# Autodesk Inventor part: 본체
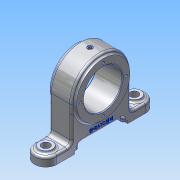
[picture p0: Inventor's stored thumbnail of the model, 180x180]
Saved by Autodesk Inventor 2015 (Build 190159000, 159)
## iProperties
Created: 2019-05
Part Number: 본체
Material: 알루미늄 6061
Document SubType Name: Modeling
Designer: user
Density: 2.7 g/cm^3
Appearance: 알루미늄 - 평지
Mass: 456.342 g
Surface Area: 318.292 cm^2
Volume: 169.015 cm^3
Author: user
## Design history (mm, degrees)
sketch "스케치1" dims "d1" = 80, "d3" = 62
  geometry: L1 (-30, 0)-(110, 0) reference; L2 (50, -40)-(2, -40); L3 (2, -40)-(2, -75); L4 (2, -75)-(-10, -75); L5 (-10, -75)-(-10, -36); L6 (0, -30)-(0, 0); L7 (0, -30)-(-6, -30); L8 (-6, -30)-(-6, -36); L9 (-6, -36)-(-10, -36); L10 (2, 40)-(2, 75); L11 (2, 75)-(-10, 75); L12 (-10, 75)-(-10, 36); L13 (-6, 30)-(-6, 36); L14 (-6, 36)-(-10, 36); L15 (0, 30)-(0, 0); L16 (0, 30)-(-6, 30); L17 (50, 40)-(2, 40); C1 r 26 at (50, 0); A1 r 40 centre (50, 0) between (50, 40) and (50, -40); 4 further points
  constraints: 32 end point, 8 symmetric about line, 4 coincident, 4 horizontal, 3 perpendicular, 2 centre point, 2 horizontal alignment, 2 point on circle, 2 vertical alignment, 1 vertical, 6 other
  dimensions: "d2" = 52 diameter of C1; "d4" = 72 diameter of L9 L1; "d5" = 60 diameter of L7 L1; "d6" = 150 diameter of L4 L1; "d8" = 60 distance from line of L5 point (50, 0); "d9" = 100 dimension on L5 (derived); "d10" = 4 distance of L8.end L5.end; "d11" = 10 distance between parallel lines of L5 L6; "d18" = 12 distance between parallel lines of L5 L3
extrude "돌출1" new body sketch "스케치1" stored distance "d19" = 30; taper "d20" = 0 deg
fillet "모깎기1" dims "d21" = 15
sketch "스케치2"
  geometry: L1 (30, 0)-(30, -20) reference; L2 (0, 0)-(30, 0) reference; L3 (0, -20)-(0, 0) reference; L4 (0, 80)-(0, 100) reference; L5 (0, 80)-(30, 80) reference; L6 (30, 100)-(30, 80) reference; C1 r 9 at (15, -20); A1 r 15 centre (15, -20) between (0, -20) and (30, -20) reference; A2 r 15 centre (15, 100) between (30, 100) and (0, 100) reference; 1 further point
  constraints: 1 centre point, 1 coincident
  dimensions: "d22" = 18 diameter of C1
extrude "돌출2" join sketch "스케치2" distance "d23" = 3; taper "d24" = 0 deg
sketch "스케치3"
  geometry: C1 r 9 at (0, 0) reference; 1 further point
hole "구멍1" sketch "스케치3" at (0, 0) diameter "d25" = 11; stored, may be unused: countersink angle "d29" = 90 deg, drill point angle "d31" = 118 deg; dims "d26" = 6, "d27" = 4, "d28" = 2, "d30" = 8
sketch "스케치4"
  geometry: C1 r 26 at (0, 50) reference; C2 r 36 at (0, 50); 1 further point
  constraints: 1 centre point, 1 coincident
  dimensions: "d32" = 72 diameter of C2
extrude "돌출3" join sketch "스케치4" distance "d33" = 3; taper "d34" = 0 deg
sketch "스케치5"
  geometry: C1 r 26 at (0, 0) reference; C2 r 26 at (0, 0) reference; 2 further points
  constraints: 1 vertical alignment
  dimensions: "d35" = 31 distance of C1.centre point (0, 31)
hole "구멍2" sketch "스케치5" at (0, 31) diameter "d36" = 3.242; stored, may be unused: countersink angle "d40" = 90 deg, drill point angle "d42" = 118 deg; dims "d37" = 6, "d38" = 7, "d39" = 1, "d41" = 8
node "작업 평면1"
sketch "스케치6"
  geometry: 1 further point
hole "구멍3" sketch "스케치6" at (0, 0) diameter "d46" = 4.917; stored, may be unused: countersink angle "d50" = 90 deg, drill point angle "d52" = 118 deg; dims "d47" = 8, "d48" = 7, "d49" = 1, "d51" = 10
node "작업 평면2"
sketch "스케치8"
  geometry: L1 (-30, 0)-(30, 0) reference; 2 further points
  constraints: 1 vertical alignment, 1 other
  dimensions: "d54" = 7 distance from line of L1 point (0, 7)
fillet "모깎기2" dims "d55" = 3
fillet "모깎기3" dims "d56" = 3
fillet "모깎기4" dims "d57" = 3
fillet "모깎기5" dims "d58" = 3
fillet "모깎기6" dims "d59" = 6
fillet "모깎기7" dims "d60" = 6
fillet "모깎기8" dims "d61" = 3
fillet "모깎기9" dims "d62" = 3
fillet "모깎기10" dims "d63" = 3
chamfer "모따기1" distance "d64" = 1; stored, may be unused: second distance "d65" = 2, angle "d66" = 45 deg
sketch "스케치9"
  geometry: C1 r 1 at (0, 0); 1 further point
  constraints: 1 centre point, 1 coincident
  dimensions: "d67" = 2 diameter of C1
extrude "돌출4" cut sketch "스케치9" stored distance "d68" = 3; taper "d69" = 0 deg
feature "엠보싱1" dims "d70" = 0.5, "d71" = 0
sketch "스케치10"
  geometry: C1 r 1.5 at (0, 26); C2 r 1.621 at (0, 31) reference; 2 further points
  constraints: 2 vertical alignment, 1 centre point, 1 other
  dimensions: "d73" = 3 diameter of C1
extrude "돌출5" cut sketch "스케치10" stored distance "d74" = 3; taper "d75" = 0 deg
node "솔리드1"
mirror "대칭1"
pattern_circular "원형 패턴1" dims angle "d44" = 360 deg
mirror "대칭2"
mirror "대칭3"
mirror "대칭4"
node "투영된 루프1"
node "투영된 루프2"
node "투영된 루프3"
other parameters: "d53" = 44
